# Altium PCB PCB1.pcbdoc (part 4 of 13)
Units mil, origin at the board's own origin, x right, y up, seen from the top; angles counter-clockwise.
Board outline 5895.51 x 5895.51 mil, 8 copper layers (Top Layer, L2_GND1, L3_SIG1, L4_GND2, L5_PWR, L6_SIG2, L7_GND3, Bottom Layer), stack 63.761 mil thick; 673 components, 558 nets, 2797 pads, 1861 vias.
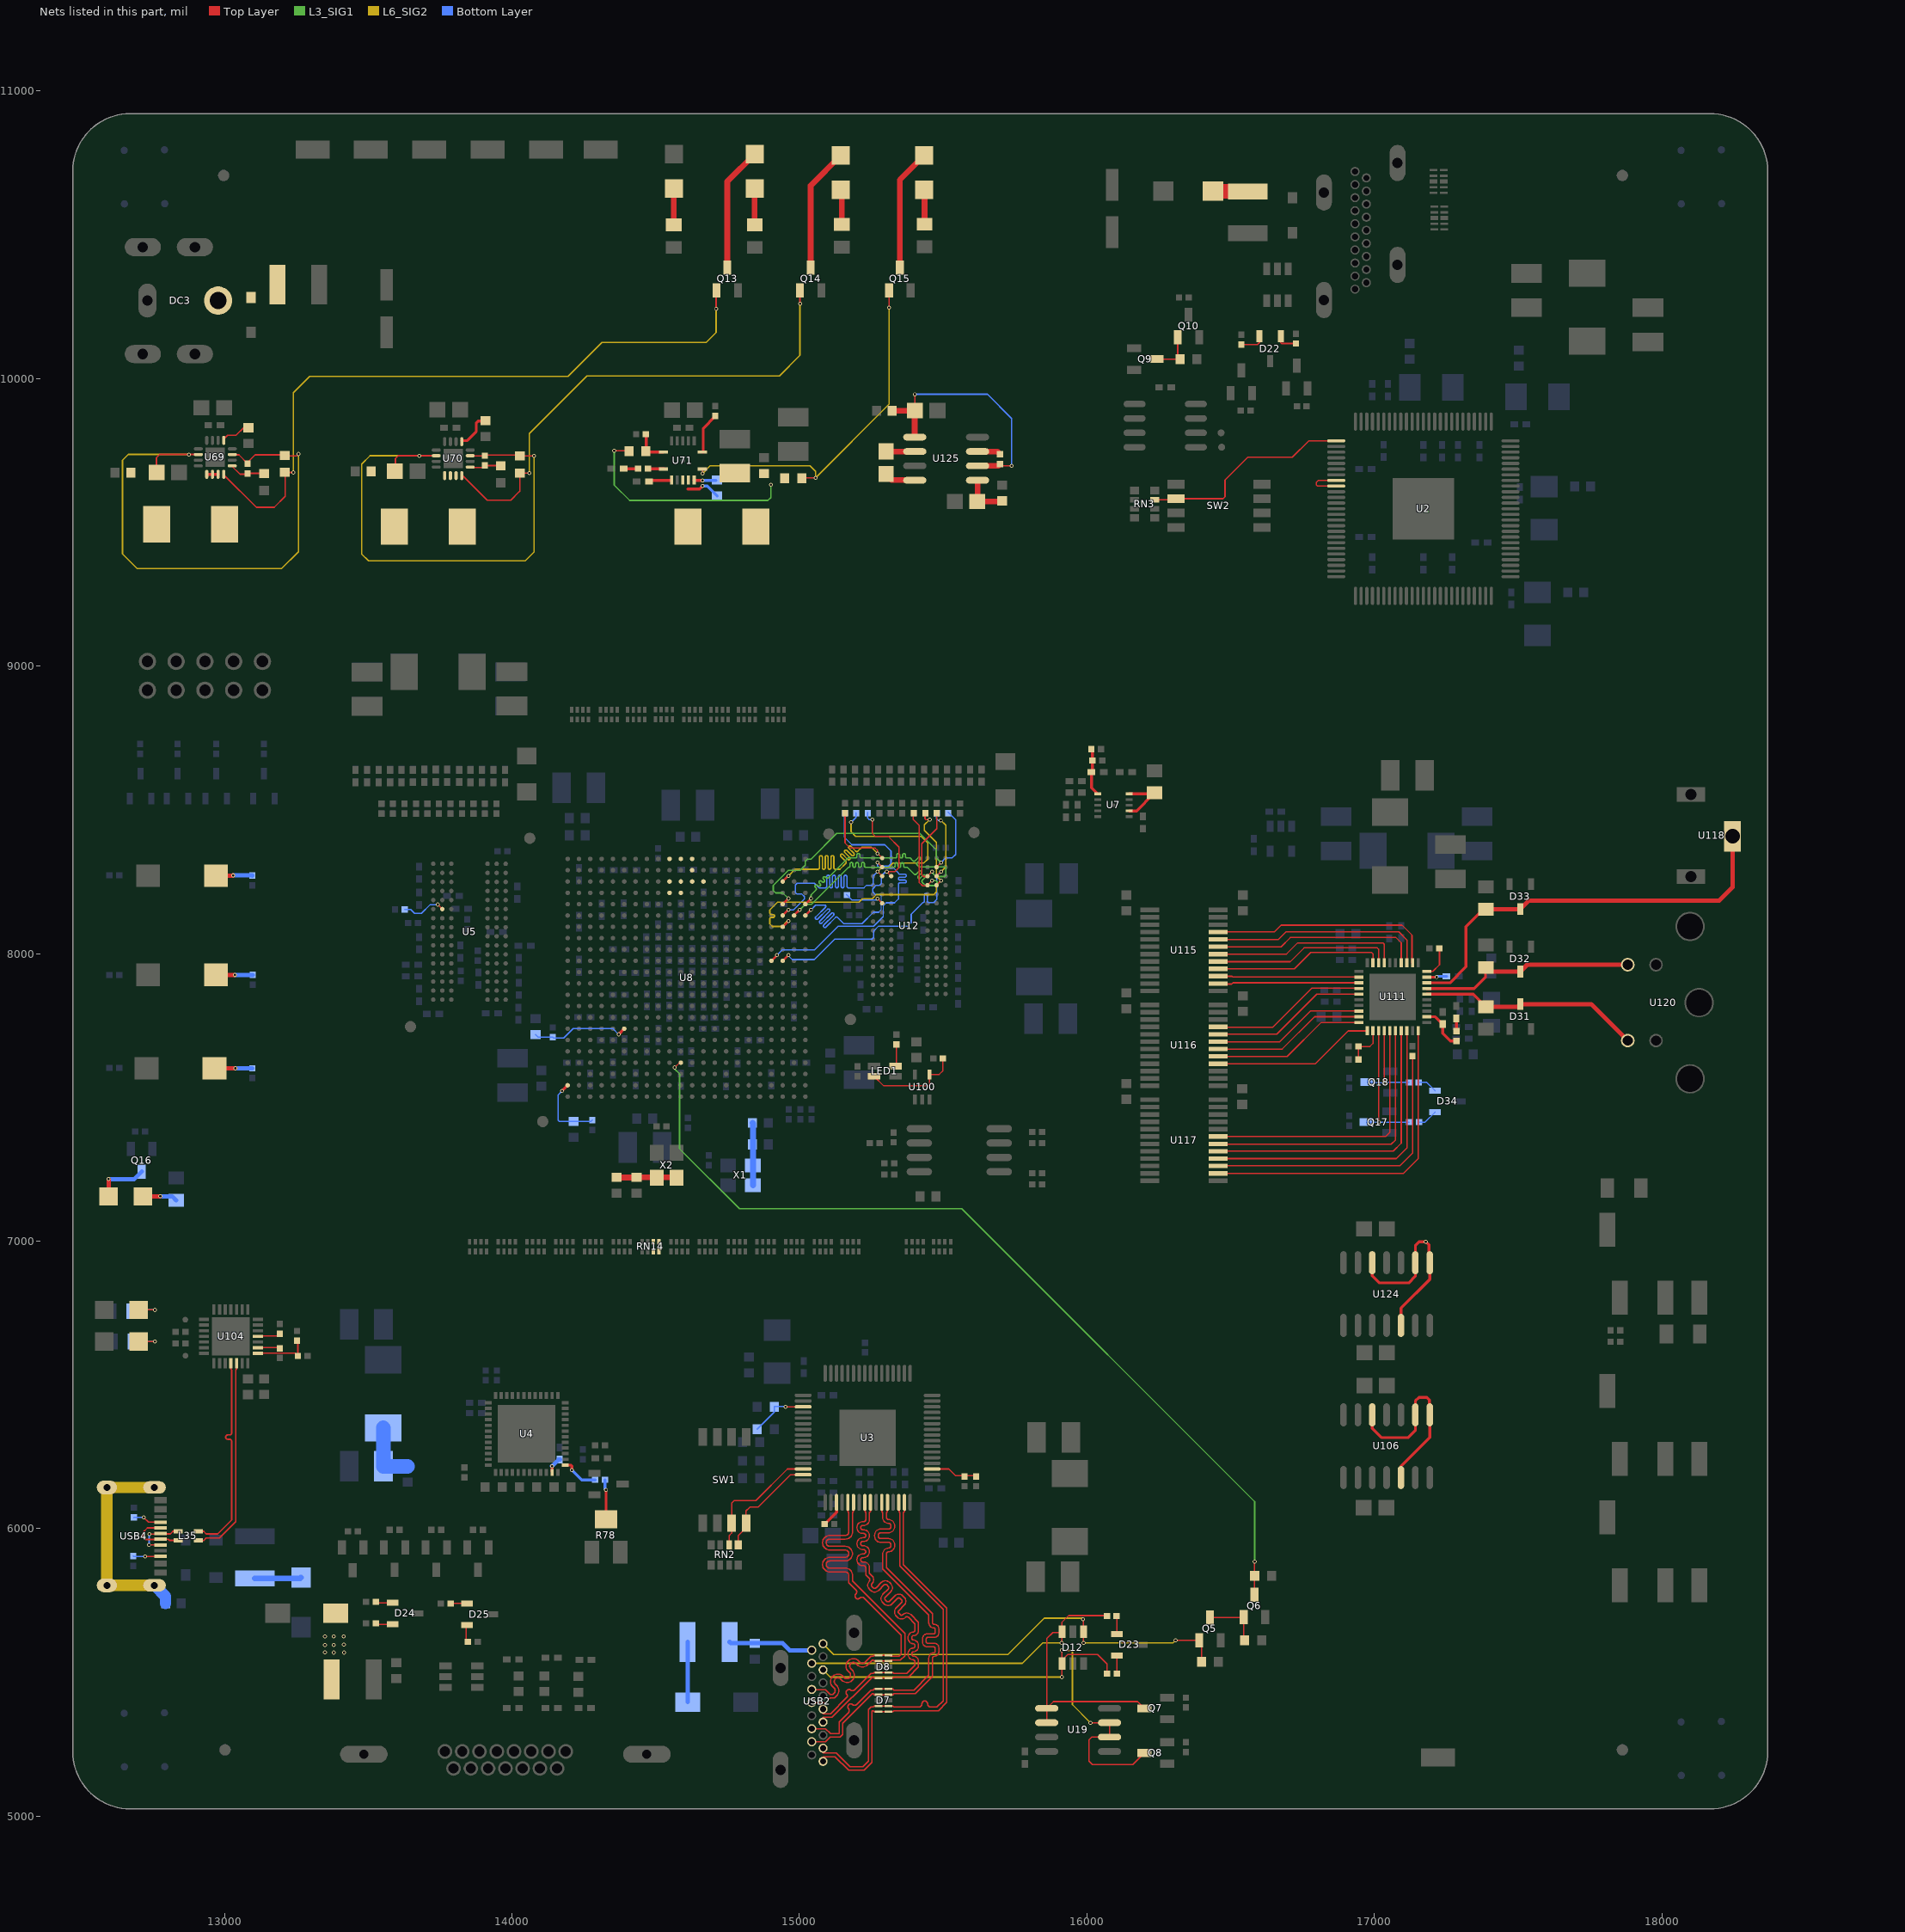
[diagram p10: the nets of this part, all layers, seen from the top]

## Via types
v1: diameter 23.62, hole 15.75, Top Layer to Bottom Layer, 621 vias
v2: diameter 13.8, hole 7.9, Top Layer to Bottom Layer, 567 vias
v3: diameter 13.78, hole 7.87, Top Layer to Bottom Layer, 529 vias
v4: diameter 13.78, hole 7.9, Top Layer to Bottom Layer, 114 vias
v5: diameter 15.75, hole 7.87, Top Layer to Bottom Layer, 16 vias
v6: diameter 24, hole 12, Top Layer to Bottom Layer, 10 vias
v7: diameter 11.81, hole 7.87, Top Layer to Bottom Layer, 4 vias

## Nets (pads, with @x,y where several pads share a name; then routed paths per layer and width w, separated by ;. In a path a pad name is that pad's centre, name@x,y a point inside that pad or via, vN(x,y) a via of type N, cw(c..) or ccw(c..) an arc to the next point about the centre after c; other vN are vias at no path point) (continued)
$1N10818: C3.2 R23.1 U8.T6 | length 343.4
  Top Layer w10: v2(14371.15,7719.16) U8.T6@14390.82,7738.84
  Bottom Layer w4.7: C3.2@14082.36,7718.44 14091.84,7708.96 R23.1@14142.36,7708.96 14145,7706.32 14180.38,7706.32 14213.06,7739 14351.31,7739 v2(14371.15,7719.16)
$1N14404: C4.2 R5.1 U8.AA1 | length 257.8
  Top Layer w10: v2(14174.29,7522.32) U8.AA1@14193.96,7542
  Bottom Layer w4.7: v2(14174.29,7522.32) 14160.52,7508.56 14160.52,7420.83 14164.83,7416.53 C4.2@14214.71,7416.53 14275.23,7416.53 R5.1@14279.71,7421.01
$1N21578: R26.1 U5.L8 | length 155
  Top Layer w4.7: v2(13742.12,8170.48) U5.L8@13757.87,8154.74
  Bottom Layer w4.7: R26.1@13627.58,8153.53 13647.83,8153.53 13661.36,8140 13685.36,8140 13715.84,8170.48 v2(13742.12,8170.48)
$1N30667: R53.1 U12.L8 | length 140
  Top Layer w4.7: v2@15272.12,8190.48 U12.L8@15287.87,8174.74
  Bottom Layer w4.7: R53.1@15164.01,8205.01 15182.88,8186.15 15267.78,8186.15 v2@15272.12,8190.48
  other v2: 15272.12,8190.6
$1N37312: R78.2 R80.2 | length 138.6
  Top Layer w10: R78.2@14327.36,6033.09 v3(14327.36,6135)
  Bottom Layer w10: R80.2@14323.4,6170 14323.4,6138.96 v3(14327.36,6135)
$1N37670: C110.1 U4.35 | length 57
  Top Layer w10: U4.35@14138.99,6198.75 14139.83,6199.58 v3(14139.83,6217.71)
  Bottom Layer w15: v3(14139.83,6217.71) 14162.01,6239.89 14166.76,6239.89 C110.1@14167.9,6241.03
$1N37860: R80.1 U4.37 | length 133.7
  Top Layer w10: U4.37@14185.22,6221.73 14185.95,6221 14205.36,6221 14208.36,6218 v3(14208.36,6204)
  Bottom Layer w10: v3(14208.36,6204) 14242.36,6170 R80.1@14289.32,6170
$1N45009: D5.1 U18.1
  other v3: 13415.19,5625.57
  other v4: 13380.45,5569.31 13415.81,5569.31 13349.7,5569.82 13349.7,5595.96 13380.45,5595.96 13415.43,5596.53 13349.7,5625.17 13380.96,5625.17
$1N52484: C119.1 R96.2 R97.2 U7.1 | length 167.5
  Top Layer w10: R96.2@16015.32,8711 16019.32,8707 R97.2@16019.32,8671 16019.32,8634.42 C119.1@16015.9,8631 16015.9,8576.75 U7.1@16037.24,8555.4
$1N52936: L1.1 U7.7 U7.10 | length 198.2
  Top Layer w10: U7.7@16147.47,8496.3 16172.7,8496.3 L1.1@16231.8,8555.4 ; U7.10@16147.47,8555.4 L1.1@16231.8,8555.4 ; L1.1@16235.36,8558.96 L1.1@16231.8,8555.4
$1N60209: R98.1 U3.19 | length 92.9
  Top Layer w10: R98.1@15087.32,6016 15129.09,6057.77 U3.19@15129.09,6091.59
$1N62286: R102.1 R103.2 U3.35 | length 163.2
  Top Layer w4.7: U3.35@15461.77,6207.73 15519.63,6207.73 15543.36,6184 15612.4,6184 R103.2@15614.36,6182.04
$1N62796: C148.2 U23.2 X2.1 X2.4 | length 209.8
  Top Layer w20: U23.2@14363.7,7221.6 C148.2@14433.7,7221.6 14572.28,7221.6 X2.1@14573.15,7220.73
$1N62811: C147.2 U22.2 X1.1 X1.4 | length 301.5
  Bottom Layer w4.7: C147.2@14837.09,7336 C147.2@14838.64,7334.45 ; U22.2@14837.14,7411.52 U22.2@14837.1,7411 14837.14,7337.8 14838.64,7336.3 C147.2@14839.47,7335.47 ; X1.4@14838.64,7258.59 X1.4@14842.39,7262.34
  Bottom Layer w20: U22.2@14837.1,7411 14838.64,7409.45 14838.64,7336.3 14838.64,7334.45 14838.64,7258.59 X1.1@14838.64,7194.53
$1N63393: D11.1 U24.1 | length 209
  Bottom Layer w15: D11.1@14611.36,5397 U24.1@14611.39,5606
$1N63667: Q5.3 Q6.1 U26.1 | length 199.9
  Top Layer w4.7: Q5.3@16427.98,5691.08 16544.32,5691.08 Q6.1@16545.58,5692.34 16545.58,5614.45 U26.1@16548.32,5611.71
$1N80606: U2.8 U2.9 | length 151.1
  Top Layer w4.7: U2.9@16867.21,9625.74 16802.62,9625.74 16798.36,9630 16798.36,9639 16804.78,9645.42 U2.8@16867.21,9645.42
$1N82813: Q9.3 Q10.1 U31.1 | length 159.8
  Top Layer w4.7: Q9.3@16242.63,10067.36 U31.1@16323.6,10067.36 16315.86,10075.1 Q10.1@16315.86,10142.99
$1N83117: D17.2 F1.1 | length 159.5
  Top Layer w50: D17.2@16438.67,10651 16595.33,10651 F1.1@16597.36,10648.97
$1N87324: L22.1 U69.1 U69.2 U69.3 | length 39.4
  Top Layer w10: U69.1@12938.75,9666.67 U69.2@12958.44,9666.67 U69.3@12978.12,9666.67
$1N87327: C195.2 U69.9 | length 100
  Top Layer w5: U69.9@12997.43,9788.7 13010.73,9802 13040.27,9802 13067.96,9829.7 C195.2@13080.4,9829.7
$1N87330: R134.2 R135.1 U69.5 | length 129.2
  Top Layer w5: U69.5@13025.39,9695.62 13054.14,9666.86 R135.1@13081.54,9666.86 ; R135.1@13080.36,9669.96 13141,9669.97 R134.2@13141.39,9669.58
$1N87338: C194.2 L22.2 L23.1 R133.2 R135.2 U69.7 U69.14 | length 2013.8
  Top Layer w5: C194.2@12762.71,9686.27 12763.75,9687.3 12763.75,9724.35 12775.04,9735.64 v3(12876.23,9735.64) 12908.48,9735.64 U69.14@12909.39,9734.73 ; U69.7@13025.39,9734.29 13050.65,9734.29 R135.2@13080.96,9703.98 ; R135.2@13079.02,9706.31 13107,9734.29 R133.2@13212.31,9734.29 ; R133.2@13211.73,9730.99 13251.18,9730.99 v3(13257.59,9737.4)
  L6_SIG2 w5: v3(12876.23,9735.64) 12665.61,9735.64 12645.43,9715.47 12645.43,9389.97 12696.59,9338.82 13198.99,9338.82 13257.59,9397.41 v3(13257.59,9737.4)
  Bottom Layer w5: v3(13257.59,9737.4) v3@13257.59,9738.18
$1N88386: L24.1 U70.1 U70.2 U70.3
$1N88389: C198.2 U70.9 | length 124.6
  Top Layer w10: U70.9@13825.8,9783.89 13844.75,9783.89 13875.94,9815.08 13875.94,9844.23 13883.22,9851.51 13904.5,9851.51 C198.2@13905.08,9852.1
$1N88392: R137.2 R138.1 U70.5 | length 118.5
  Top Layer w5: U70.5@13855.72,9689.87 13898.57,9689.87 13908.19,9699.48 13910.81,9696.86 R137.2@13969.1,9696.86
$1N88397: C197.2 L24.2 L25.1 R136.2 R138.2 U70.7 U70.14 | length 1896.6
  Top Layer w5: C197.2@13593.87,9673.91 13594.74,9674.78 13594.74,9721.56 13604.8,9731.62 U70.14@13736.4,9731.62 ; U70.7@13857.76,9730.67 R138.2@13905.85,9730.67 ; R138.2@13903.92,9733.26 14024.88,9733.26 R136.2@14025.76,9732.38 ; R136.2@14028.38,9728.01 14031.29,9730.93 v3(14077.35,9730.93)
  L6_SIG2 w5: v4(13677.81,9731.18) 13506.59,9731.18 13477.58,9702.17 13477.58,9389.05 13501.16,9365.48 14046.51,9365.48 14077.35,9396.31 v3(14077.35,9730.93)
$1N88827: R139.2 U71.1 | length 140.8
  Top Layer w10: U71.1@14665.56,9744.35 14665.56,9826.95 R139.2@14706.69,9868.08
$1N88869: C200.2 U71.9 | length 80
  Top Layer w10: C200.2@14476.25,9641.36 14480.42,9645.52 U71.9@14554.58,9645.52
$1N89025: R140.2 U71.8 | length 57.8
  Top Layer w10: R140.2@14471.94,9685.76 U71.8@14529.71,9685.76
$1N89029: C201.2 R140.1 | length 47.5
  Top Layer w10: C201.2@14389.38,9685.33 14436.59,9685.33 R140.1@14436.81,9685.11
$1N89111: C202.1 U71.13 | length 77.1
  Top Layer w10: U71.13@14632.4,9645.71 v3(14663.33,9645.71)
  Bottom Layer w10: v3(14663.33,9645.71) C202.1@14709.49,9645.71
$1N89126: C202.2 L26.1 U71.11 U71.12 | length 120.6
  Top Layer w10: 14611.5,9615.43 14652.85,9615.43 v3(14662.95,9625.53)
  Bottom Layer w10: v3(14662.95,9625.53) 14679.2,9625.53 C202.2@14713.67,9591.06
$1N89349: R141.2 R142.1 U71.7 | length 123.6
  Top Layer w10: R142.1@14464.54,9746.26 R142.1@14465.84,9744.97 ; R141.2@14466.91,9806.62 14466.91,9746.05 R142.1@14465.84,9744.97 ; U71.7@14525.12,9744.11 14466.7,9744.11 R142.1@14465.84,9744.97
$1N92548: R143.1 U77.2 | length 126.6
  Top Layer w20: R143.1@14563.18,10534.34 U77.2@14563.18,10660.93
$1N92638: R144.1 U78.2 | length 126.4
  Top Layer w20: R144.1@14844.36,10534.34 U78.2@14844.36,10660.74
$1N93481: Q13.3 U78.1 | length 434.2
  Top Layer w20: Q13.3@14749.36,10385.37 14749.36,10685.22 U78.1@14844.36,10780.22
$1N93486: Q13.1 R133.1 U69.4 | length 2362.2
  Top Layer w5: U69.4@12999.69,9663.8 13111.61,9551.88 13173.26,9551.88 13211.29,9589.92 13211.29,9670.36 13210.42,9671.24 13212.38,9673.19 v3(13239.94,9673.19) ; v3(14710.43,10241.74) 14710.43,10300.9 Q13.1@14711.3,10301.78
  L6_SIG2 w5: v3(13239.94,9673.19) 13239.94,9949.99 13296.81,10006.87 14194.9,10006.87 14313.43,10125.4 14675.96,10125.4 14710.43,10159.87 v3(14710.43,10241.74)
$1N93678: R145.1 U79.2 | length 122.1
  Top Layer w20: U79.2@15144.36,10656.26 15147.36,10653.26 R145.1@15147.36,10535.37
$1N93680: Q14.3 U79.1 | length 433.9
  Top Layer w20: Q14.3@15039.36,10385.37 15039.36,10670.74 U79.1@15144.36,10775.74
$1N93699: Q14.1 R136.1 U70.4 | length 1772.7
  Top Layer w5: U70.4@13827.04,9663.81 13914.45,9576.4 13996.01,9576.4 14025.74,9606.13 14027.93,9606.13 14027.93,9670.84 14060.13,9670.84 v3(14060.3,9671.01) ; Q14.1@15000.94,10314.4 15001.99,10313.35 v3(15001.99,10259.57)
  L6_SIG2 w5: v3(14060.3,9671.01) 14060.3,9808.64 14260.65,10009 14930.32,10009 15001.99,10080.67 v3(15001.99,10259.57)
$1N93752: C206.2 L26.2 L27.1 R142.2 R146.2 | length 784.3
  Top Layer w5: v3(14356.08,9748.56) 14356.47,9748.17 R142.2@14405.43,9748.17
  L3_SIG1 w5: v3(14356.08,9748.56) 14356.08,9629.42 14409.63,9575.86 14890.88,9575.86 14900.83,9585.81 v3(14900.83,9630.4)
$1N93902: R147.1 U80.2 | length 120.3
  Top Layer w20: U80.2@15434.36,10656.26 15435.36,10655.26 R147.1@15435.36,10536.37
$1N93904: Q15.3 U80.1 | length 425.6
  Top Layer w20: Q15.3@15349.36,10385.37 15349.36,10690.74 U80.1@15434.36,10775.74
$1N93914: Q15.1 R146.1 U71.14 | length 1259.1
  Top Layer w5: v3(14662.94,9669.34) U71.14@14662.94,9685.27 ; R146.1@15009.06,9654.28 15055.98,9654.28 v3(15056.51,9654.81) ; Q15.1@15310.3,10309.03 15312.41,10306.92 v3(15312.41,10245.9)
  L6_SIG2 w5: v3(14662.94,9669.34) 14689.48,9695.88 15037.37,9695.88 15056.51,9676.74 v3(15056.51,9654.81) 15312.41,9910.71 v3(15312.41,10245.9)
$1N104683: D20.1 DC3.3 F2.2
$1N105607: R148.1 U81.2 | length 121.2
  Top Layer w15: U81.2@12717.1,7156 v3(12777.36,7156)
  Bottom Layer w15: v3(12777.36,7156) 12817.99,7156 R148.1@12832.36,7141.63
$1N105608: Q16.3 U81.1 | length 185.7
  Top Layer w15: v3(12597.36,7216) 12597.36,7156.26 U81.1@12597.62,7156
  Bottom Layer w15: v3(12597.36,7216) 12686.73,7216 Q16.3@12712.36,7241.63
$1N105776: R196.2 SW3.2 | length 127.7
  Top Layer w15: SW3.2@12970.47,8271 13029.36,8271 v3(13030.36,8272)
  Bottom Layer w15: v3(13030.36,8272) 13096.4,8272 R196.2@13097.36,8271.04
$1N106443: C216.2 L32.2 L33.1 | length 218.7
  Bottom Layer w50: L32.2@13552.55,6351.08 13553.1,6350.53 C216.2@13553.1,6217 13553.54,6216.56 L33.1@13637.36,6216.56
$1N164530: D22.2 R111.2 | length 88.1
  Top Layer w4.7: R111.2@16537.36,10117.96 16593.32,10117.96 16600.36,10125 16600.36,10146.42 D22.2@16599.79,10146.98
$1N164545: D22.1 R110.1 | length 76.9
  Top Layer w4.7: D22.1@16674.59,10146.98 16674.36,10146.75 16674.36,10124 16676.77,10121.58 R110.1@16727.19,10121.58
$1N164557: D23.1 R106.1 | length 63.5
  Top Layer w4.7: R106.1@16103.4,5697 16103.95,5696.45 D23.1@16103.95,5633.73
$1N164561: D23.2 R107.2 | length 62.8
  Top Layer w4.7: D23.2@16103.95,5558.93 16104.35,5558.53 R107.2@16104.35,5496.33
$1N164584: D24.2 R91.2 | length 63.8
  Top Layer w4.7: R91.2@13528.4,5667.67 13589.83,5667.67 D24.2@13591.49,5666.01
$1N164596: D24.1 R90.1 | length 60.6
  Top Layer w4.7: R90.1@13526.08,5746.04 13529.62,5742.5 D24.1@13585.19,5742.5
$1N164661: D25.1 R94.1 | length 57.3
  Top Layer w4.7: R94.1@13787.4,5740 13843.75,5740 D25.1@13844.41,5739.35
$1N164665: D25.2 R95.2 | length 63.8
  Top Layer w4.7: R95.2@13841.35,5604.79 13841.35,5663.23 D25.2@13845.12,5667
$1N212426: LED1.3 R154.2 U100.4 | length 338.5
  Top Layer w4.7: LED1.3@15259.96,7573.28 15293.24,7540 15448.36,7540 15452.95,7544.59 U100.4@15452.95,7579.31 15453.64,7580 15486.36,7580 15499.4,7593.04 R154.2@15499.4,7636
$1N226069: U3.3 U101.1 U102.2 | length 203.7
  Top Layer w4.7: v3(14951.36,6424.27) U3.3@15012.95,6424.27
  Bottom Layer w4.7: U102.2@14853.32,6346.36 14912.64,6405.68 U101.1@14912.64,6424.06 14913.58,6425 14951.36,6425 v3(14951.36,6424.27)
$1N298643: R197.2 SW4.2 | length 127.9
  Top Layer w15: SW4.2@12970.47,7926 v3(13036.36,7926)
  Bottom Layer w15: v3(13036.36,7926) R197.2@13098.32,7926
$1N298747: R198.2 SW5.2 | length 131.9
  Top Layer w15: SW5.2@12965.47,7601 v3(13038.36,7601)
  Bottom Layer w15: v3(13038.36,7601) R198.2@13097.32,7601
$1N329198: U8.D10
$1N329200: U8.C10
$1N329204: U8.A10
$1N329206: U8.C11
$1N329208: U8.A11
$1N329210: U8.D11
$1N329212: U8.C12
$1N329214: U8.B12
$1N329216: U8.A12
$1N329253: U8.C13
$1N373188: LED1.1 R185.2 | length 76.3
  Top Layer w4.7: LED1.1@15334.76,7608.72 15337.36,7611.31 R185.2@15337.36,7683.96
$1N419363: RN14.3
$1N419365: RN14.4
$1N419415: RN14.6
$1N419417: RN14.5
$2N4528: R157.1 R158.2 U104.8 | length 198
  Top Layer w4: U104.8@13116.29,6609.86 U104.8@13116.85,6610.42 ; R157.1@13245.79,6610.42 R157.1@13246.35,6609.86
  Top Layer w4.7: U104.8@13116.85,6610.42 13117.03,6610.6 13245.61,6610.6 R157.1@13245.79,6610.42 ; R157.1@13246.35,6609.86 R157.1@13255.65,6600.56 13255.65,6650.56 R158.2@13252.69,6653.52
$2N4529: R31.2 U104.9 | length 77.2
  Top Layer w4.7: U104.9@13116.29,6629.54 13190.75,6629.54 R31.2@13192.69,6627.6
$2N4531: U104.11 U105.1 | length 76.5
  Top Layer w4.7: U104.11@13119.47,6670.56 13184.73,6670.56 U105.1@13192.69,6678.52
$2N4874: L35.1 USB4.6 USB4.8 | length 160.4
  Top Layer w5.1: v3(12738.2,5943.51) 12738.39,5943.71 USB4.8@12778.52,5943.71 ; v3(12738.86,5981.15) 12776.59,5981.15 USB4.6@12778.52,5983.08 ; 12800.85,5982.03 12811.93,5982.03 12820.6,5990.7 L35.1@12838.89,5990.7
  Bottom Layer w5.1: v3(12738.2,5943.51) 12738.2,5980.48 v3(12738.86,5981.15)
$2N4875: L35.2 USB4.5 USB4.7 | length 210.3
  Top Layer w5.1: USB4.7@12778.05,5962.55 12726.69,5962.55 12716.73,5972.51 12716.73,5986.9 12732.58,6002.76 USB4.5@12778.52,6002.76 ; USB4.7@12778.52,5963.39 12805.4,5963.39 12809.52,5959.26 L35.2@12838.95,5959.26
$2N4881: R121.1 USB4.10 | length 91.4
  Top Layer w4.7: v3(12724.5,5903.88) USB4.10@12773.87,5903.88
  Bottom Layer w4.7: R121.1@12682.88,5904.77 12683.76,5903.88 v3(12724.5,5903.88)
$2N4882: R120.1 USB4.4 | length 101.4
  Top Layer w4.7: v3(12719.85,6039.09) 12735.94,6023.01 USB4.4@12779.18,6023.01
  Bottom Layer w4.7: R120.1@12684.73,6038.35 12685.46,6039.09 v3(12719.85,6039.09)
$2N4887: L36.1 USB4.13 USB4.14 | length 750
  L6_SIG2 w40: USB4.14@12756.86,5802.95 USB4.14@12591.51,5802.96 USB4.13@12591.51,6143.51 USB4.13@12756.87,6143.5
  Bottom Layer w40: USB4.14@12756.86,5802.95 12795.25,5764.58 L36.1@12795.25,5740.16
$2N5766: D29.2 F3.1 | length 162
  Bottom Layer w20: F3.1@13105.67,5827.26 13263.3,5827.26 D29.2@13266.36,5830.32
$2N6016: R164.1 U108.2 | length 129.2
  Top Layer w4.7: U108.2@12702.1,6651 v3(12758.36,6651)
  Bottom Layer w4.7: R164.1@12685.47,6651 v3(12758.36,6651)
$2N6092: R165.1 U109.2 | length 135
  Top Layer w4.7: U109.2@12702.1,6761 v3(12758.36,6761)
  Bottom Layer w4.7: R165.1@12681.73,6756 12686.73,6761 v3(12758.36,6761)
$2N13136: C341.1 R173.1 U111.22 | length 157
  Top Layer w10: U111.22@17181.77,7780.37 17211.53,7780.37 C341.1@17237.36,7754.54 17237.36,7723 17264.4,7695.96 R173.1@17285.36,7695.96
$2N13145: C342.1 R173.2 | length 44.5
  Top Layer w10: C342.1@17285.07,7774.42 17285.07,7730.33 R173.2@17285.36,7730.04
$2N15480: D34.1 R182.1 | length 69.9
  Bottom Layer w4.7: R182.1@17155.4,7414 17176.4,7414 D34.1@17211,7448.6
$2N15481: D34.2 R183.2 | length 68.4
  Bottom Layer w4.7: R183.2@17154.4,7552 17182.4,7552 D34.2@17211,7523.4
$3N1865: C353.2 U125.2 | length 92.9
  Top Layer w20: C353.2@15302.45,9743.07 15305.22,9745.84 15392.15,9745.84 U125.2@15393.61,9744.38
$3N1869: C353.1 U125.4 | length 106.7
  Top Layer w20: C353.1@15298.52,9669.62 15321.57,9646.57 U125.4@15395.67,9646.57
$3N1948: R195.2 U125.7 | length 82.4
  Top Layer w20: U125.7@15619.51,9746 15688.12,9746 R195.2@15697.85,9736.27
$3N2377: C351.2 L44.2 R195.1 U125.1 U125.6 | length 888
  Top Layer w5: C351.2@15401.21,9887.92 v3(15401.21,9945) ; R195.1@15697.85,9702.19 15704.04,9696 v3(15738.36,9696)
  Top Layer w20: L44.2@15323.11,9887.91 15401.19,9887.91 U125.1@15401.21,9796 ; U125.6@15619.51,9696 15691.66,9696 R195.1@15697.85,9702.19
  Bottom Layer w5: v3(15401.21,9945) 15654.36,9945 15738.36,9861 v3(15738.36,9696)
$3N2455: C352.2 L45.1 U125.5 | length 157.9
  Top Layer w20: U125.5@15619.51,9646 15619.51,9573.15 C352.2@15618.82,9572.47 15702.02,9572.47 L45.1@15702.66,9573.11
$3N2639: U106.1 U106.2 U106.5 U106.12 | length 693.2
  Top Layer w10: U106.5@16992.36,6396.02 16992.36,6349 17024.36,6317 17118.36,6317 17142.36,6341 U106.2@17142.36,6396.02 17142.36,6444 17155.36,6457 17182.36,6457 17191.36,6448 17191.36,6397.02 U106.1@17192.36,6396.02 17192.36,6318 17092.36,6218 U106.12@17092.36,6177.98
$3N2658: U124.1 U124.2 U124.5 U124.12 | length 701.6
  Top Layer w10: U124.5@16992.36,6925.02 16992.36,6879.9 17017.26,6855 17119.36,6855 17142.36,6878 U124.2@17142.36,6925.02 17142.36,6985 17155.36,6998 v4(17178.36,6998) 17189.36,6987 17189.36,6928.02 U124.1@17192.36,6925.02 17192.36,6867 17092.36,6767 U124.12@17092.36,6706.98
ADV7393_ALSB: R171.1 R172.1 U111.12 | length 143.8
  Top Layer w4.7: R171.1@16944.08,7631.79 R172.1@16944.08,7676.79 16944.29,7677 16984.36,7677 16994.76,7687.4 U111.12@16994.76,7731.16
ADV7393_CMP: U111.29 U112.1 | length 70.3
  Top Layer w10: U111.29@17181.77,7918.17 v3(17216.36,7918.17)
  Bottom Layer w10: v3(17216.36,7918.17) 17219.19,7921 U112.1@17250.9,7921
ADV7393_DAC1: D33.3 R174.1 U111.28 U118.1 | length 1460.7
  Top Layer w10: U111.28@17181.77,7898.48 17262.84,7898.48 17318.36,7954 17318.36,8094 17377.99,8153.63 R174.1@17387.36,8153.63
  Top Layer w15: R174.1@17387.36,8153.63 17388.37,8154.64 D33.3@17507.36,8154.64 17537.41,8184.69 18199.51,8184.69 18245.44,8230.63 U118.1@18245.44,8408.1
ADV7393_DAC2: D32.3 R175.2 U111.27 U120.4 | length 764.7
  Top Layer w10: U111.27@17181.77,7878.8 17347.16,7878.8 17386.36,7918 17386.36,7950.63 R175.2@17387.36,7951.63
  Top Layer w15: R175.2@17386.36,7950.63 17399.35,7937.64 D32.3@17507.36,7937.64 17531.02,7961.3 U120.4@17881.05,7961.3
ADV7393_DAC3: D31.3 R176.2 U111.26 U120.3 | length 773.7
  Top Layer w10: U111.26@17181.77,7859.11 17343.62,7859.11 R176.2@17387.36,7815.37
  Top Layer w15: R176.2@17387.36,7815.37 17498.37,7815.37 D31.3@17507.36,7824.36 17754.21,7824.36 U120.3@17881.05,7697.52
ADV7393_HS: U111.33 U115.20 | length 745.9
  Top Layer w4.7: U115.20@16469.8,8048.64 16470.23,8049.08 16665.98,8049.08 16692.36,8075.45 17084.98,8075.45 17112.87,8047.56 U111.33@17112.87,7967.38
ADV7393_P0: U111.34 U115.19 | length 710.3
  Top Layer w4.7: U115.19@16474.05,8023.28 16474.35,8023.59 16675.21,8023.59 16707.33,8055.7 17075.1,8055.7 17093.19,8037.61 U111.34@17093.19,7967.38
ADV7393_P1: U111.37 U115.18 | length 636.3
  Top Layer w4.7: U115.18@16480.95,7998.54 16694.44,7998.54 16733.14,8037.24 17029.43,8037.24 17034.13,8032.54 U111.37@17034.13,7967.38
ADV7393_P2: U111.38 U115.17 | length 615.3
  Top Layer w4.7: U115.17@16468.99,7971.78 16707.21,7971.78 16755.44,8020 17009.75,8020 17014.45,8015.3 U111.38@17014.45,7967.38
ADV7393_P3: U111.39 U115.16 | length 573.7
  Top Layer w4.7: U115.16@16478.84,7946.24 16479.6,7947 16721.85,7947 16778.85,8004 16990.06,8004 16994.76,7999.3 U111.39@16994.76,7967.38
ADV7393_P4: U111.2 U115.15 | length 466.9
  Top Layer w4.7: U115.15@16479.92,7921.3 16480.22,7921 16504.36,7921 16507.19,7918.17 U111.2@16945.55,7918.17
ADV7393_P5: U111.3 U115.14 | length 474.8
  Top Layer w4.7: U115.14@16472.91,7894.69 16473.6,7894 16503.36,7894 16507.84,7898.48 U111.3@16945.55,7898.48
ADV7393_P6: U111.4 U116.21 | length 526.1
  Top Layer w4.7: U116.21@16476.24,7744.2 16476.44,7744 16646.36,7744 16782.16,7879.8 16944.55,7879.8 U111.4@16945.55,7878.8
ADV7393_P7: U111.5 U116.20 | length 530.1
  Top Layer w4.7: U116.20@16473.09,7720 16660.36,7720 16799.47,7859.11 U111.5@16945.55,7859.11
ADV7393_P8: U111.8 U116.19 | length 512.6
  Top Layer w4.7: U116.19@16477.49,7693.58 16478.07,7693 16670.36,7693 16777.42,7800.06 U111.8@16945.55,7800.06
ADV7393_P9: U111.9 U116.18 | length 511
  Top Layer w4.7: U116.18@16481.17,7667.87 16481.3,7668 16679.36,7668 16791.73,7780.37 U111.9@16945.55,7780.37
ADV7393_P10: U111.10 U116.17 | length 526.7
  Top Layer w4.7: U116.17@16468.1,7641.9 16468.2,7642 16696.36,7642 16815.05,7760.69 U111.10@16945.55,7760.69
ADV7393_P11: U111.11 U116.16 | length 548
  Top Layer w4.7: U116.16@16474.41,7617 16794.36,7617 16908.52,7731.16 U111.11@16975.08,7731.16
ADV7393_P12: U111.15 U117.19 | length 936.2
  Top Layer w4.7: U117.19@16476.47,7364.51 16476.98,7364 17039.23,7364 17053.82,7378.59 U111.15@17053.82,7731.16
ADV7393_P13: U111.16 U117.18 | length 986.6
  Top Layer w4.7: U117.18@16472.16,7337.02 17058.36,7337 17073.5,7352.14 U111.16@17073.5,7731.16
ADV7393_P14: U111.17 U117.17 | length 1036
  Top Layer w4.7: U117.17@16459.21,7312.72 16459.49,7313 17065.36,7313 17093.19,7340.83 U111.17@17093.19,7731.16
ADV7393_P15: U111.18 U117.16 | length 1062.1
  Top Layer w4.7: U117.16@16473.98,7287.96 16474.94,7287 17076.36,7287 17112.87,7323.51 U111.18@17112.87,7731.16
ADV7393_RESET: U111.20 U117.14 | length 1141.5
  Top Layer w4.7: U117.14@16476.68,7235.34 16477.01,7235 17100.36,7235 17152.24,7286.88 U111.20@17152.24,7731.16
ADV7393_RSET: R170.1 U111.30 | length 111.6
  Top Layer w4.7: U111.30@17181.77,7937.85 17203.21,7937.85 17226.36,7961 17226.36,8017.04 R170.1@17225.4,8018
ADV7393_SCL: Q18.3 R183.1 U111.14 | length 325.3
  Top Layer w4.7: v3(17034.13,7552) U111.14@17034.13,7731.16
  Bottom Layer w4.7: Q18.3@16975.99,7553 16977.99,7551 17034.13,7551 v3(17034.13,7552) R183.1@17120.32,7552
ADV7393_SDA: Q17.3 R182.2 U111.13 | length 465.9
  Top Layer w4.7: U111.13@17014.45,7731.16 17014.45,7414.91 v3(17015.36,7414)
  Bottom Layer w4.7: Q17.3@16972.99,7414 v3(17015.36,7414) R182.2@17121.32,7414
ADV7393_VS: U111.32 U115.21 | length 788.1
  Top Layer w4.7: U115.21@16464.55,8074.61 16465.1,8075.16 16651.41,8075.16 16675.13,8098.88 17095.9,8098.88 17130.59,8064.18 U111.32@17130.59,7966.57
BSEL: RN2.5 SW1.4 U3.15 | length 379.6
  Top Layer w4.7: RN2.5@14787.6,5944.44 14787.36,5944.68 14787.36,5976 14814.36,6003 SW1.4@14814.36,6019 14814.36,6062 14827.36,6075 14856.36,6075 14969.41,6188.05 U3.15@15012.95,6188.05
BUFFER_27M_OUT: R177.1 U117.15 | length 1019.8
  Top Layer w4.7: U117.15@16469.13,7262.96 16470.09,7262 17088.36,7262 17132.36,7306 R177.1@17132.36,7643.96
D+: L35.4 U104.4 | length 714.8
  Top Layer w5.1: L35.4@12909.82,5990.76 12928.12,5990.76 12936.83,5982.05 12977.25,5982.05 13025.48,6030.28 13025.48,6303.64 ccw(c13017.98,6303.64) 13017.98,6311.14 13011.86,6311.14 cw(c13011.86,6318.64) 13011.86,6326.14 13017.98,6326.14 ccw(c13017.98,6333.64) 13025.48,6333.64 13025.48,6552.15 13022.69,6554.94 U104.4@13022.69,6575.31
D-: L35.3 U104.5 | length 708.8
  Top Layer w5.1: L35.3@12909.8,5959.24 12928.12,5959.24 12936.83,5967.95 12983.09,5967.95 13039.58,6024.44 13039.58,6552.15 13042.38,6554.94 U104.5@13042.38,6575.31
DFO: RN3.7 SW2.2 U2.1 | length 749.9
  Top Layer w4.7: RN3.7@16236.01,9578.75 16306.11,9578.75 SW2.2@16309.36,9582 16473.36,9582 16480.36,9589 16480.36,9647 16559.36,9726 16714.36,9726 16771.58,9783.22 U2.1@16867.21,9783.22
DSEL: RN2.6 SW1.3 U3.14 | length 445.8
  Top Layer w4.7: RN2.6@14756.11,5944.44 14756.36,5944.69 14756.36,5977 14764.36,5985 SW1.3@14764.36,6019 14764.36,6089 14773.36,6098 14848.36,6098 14958.09,6207.73 U3.14@15012.95,6207.73
DVI_5V: C149.2 U24.2 USB2.18 | length 297.3
  Bottom Layer w15: U24.2@14757.33,5606 14761.77,5601.56 C149.2@14844.36,5601.56 14941.8,5601.56 14965.82,5577.54 USB2.18@15042.85,5577.54
DVI_C_CLK+: D8.4 D8.7 U3.22 USB2.10 | length 1423.5
  Top Layer w4: USB2.10@15041.04,5395.8 15092.3,5395.8 15107.49,5410.99 15122.02,5410.99 15129.94,5418.91 ccw(c15111.91,5436.94) 15129.94,5454.97 15124.9,5460.02 cw(c15133.74,5468.86) 15142.58,5477.7 15147.62,5472.65 ccw(c15165.65,5490.68) 15183.68,5508.71 15178.64,5513.76 cw(c15187.48,5522.6) 15196.32,5531.44 15201.36,5526.39 ccw(c15219.39,5544.42) 15237.42,5526.39 15254.05,5543.02 15256.05,5543.02 15259.38,5539.68 D8.7@15274.77,5539.68 D8.4@15310.83,5539.68 ; U3.22@15188.15,6091.59 15188.15,6060.06 15184.8,6056.72 15184.8,5989.32 cw(c15159.3,5989.32) 15159.3,5963.82 15105.82,5963.82 ccw(c15105.82,5951.32) 15105.82,5938.82 15159.3,5938.82 cw(c15159.3,5913.32) 15159.3,5887.82 15105.82,5887.82 ccw(c15105.82,5875.32) 15105.82,5862.82 15159.3,5862.82 cw(c15159.3,5837.32) 15184.8,5837.32 15184.8,5817.66 15367.15,5635.31 15367.15,5558.61 15351.56,5543.02 15318.16,5543.02 15314.83,5539.68 D8.4@15310.83,5539.68 ; D8.4@15311.76,5538.75 D8.4@15310.83,5539.68
DVI_C_CLK-: D8.5 D8.6 U3.21 USB2.12 | length 1420.2
  Top Layer w4: USB2.12@15046.79,5440.1 15091.38,5440.1 15107.49,5423.99 15116.63,5423.99 15120.75,5428.1 ccw(c15111.91,5436.94) 15120.75,5445.78 15115.71,5450.83 cw(c15133.74,5468.86) 15151.77,5486.89 15156.81,5481.84 ccw(c15165.65,5490.68) 15174.49,5499.52 15169.45,5504.57 cw(c15187.48,5522.6) 15205.51,5540.63 15210.55,5535.58 ccw(c15219.39,5544.42) 15228.23,5535.58 15248.66,5556.02 15256.05,5556.02 15259.38,5559.35 D8.6@15274.77,5559.35 15308.74,5559.35 D8.5@15310.14,5560.76 ; U3.21@15168.46,6091.59 15168.46,6060.06 15171.8,6056.72 15171.8,5989.32 cw(c15159.3,5989.32) 15159.3,5976.82 15105.82,5976.82 ccw(c15105.82,5951.32) 15105.82,5925.82 15159.3,5925.82 cw(c15159.3,5913.32) 15159.3,5900.82 15105.82,5900.82 ccw(c15105.82,5875.32) 15105.82,5849.82 15159.3,5849.82 cw(c15159.3,5837.32) 15171.8,5837.32 15171.8,5812.28 15196.61,5787.47 cw(c15189.54,5780.4) 15196.61,5773.33 15196.35,5773.06 ccw(c15203.42,5765.99) 15210.49,5758.92 15210.75,5759.18 cw(c15217.83,5752.11) 15224.9,5759.18 15354.15,5629.93 15354.15,5563.99 15346.18,5556.02 15318.16,5556.02 15314.83,5559.35 D8.5@15309.42,5559.35
DVI_C_D0+: D8.1 D8.10 U3.25 USB2.7 | length 1424.5
  Top Layer w4: USB2.7@15082.22,5327.46 15082.22,5342.29 15083.63,5343.7 15113.8,5343.7 15254.05,5483.95 15256.05,5483.95 15259.38,5480.61 D8.10@15274.77,5480.61 15303.88,5480.61 D8.1@15303.99,5480.5 ; U3.25@15247.2,6091.59 15247.2,6060.06 15243.86,6056.72 15243.86,6032.03 cw(c15223.36,6032.03) 15223.36,6011.53 15220.54,6011.53 ccw(c15220.54,6004.03) 15220.54,5996.53 15223.36,5996.53 cw(c15223.36,5976.03) 15223.36,5955.53 15220.54,5955.53 ccw(c15220.54,5948.03) 15220.54,5940.53 15223.36,5940.53 cw(c15223.36,5920.03) 15223.36,5899.53 15220.54,5899.53 ccw(c15220.54,5892.03) 15220.54,5884.53 15223.36,5884.53 cw(c15223.36,5864.03) 15243.86,5864.03 15243.86,5845.15 15252.35,5836.66 cw(c15238.37,5822.68) 15252.35,5808.7 ccw(c15257.14,5803.91) 15252.35,5799.12 15256.92,5794.55 ccw(c15261.71,5799.34) 15266.5,5794.55 15285.27,5813.32 cw(c15299.25,5799.34) 15313.23,5813.32 15317.79,5808.76 cw(c15303.81,5794.78) 15317.79,5780.8 15299.02,5762.03 ccw(c15303.81,5757.24) 15299.02,5752.45 15303.59,5747.88 ccw(c15308.38,5752.67) 15313.17,5747.88 15331.93,5766.65 cw(c15345.92,5752.67) 15359.9,5766.65 15364.46,5762.09 cw(c15350.48,5748.11) 15364.46,5734.13 15345.69,5715.36 ccw(c15350.48,5710.57) 15345.69,5705.78 15350.26,5701.22 ccw(c15355.05,5706) 15359.83,5701.22 cw(c15373.82,5687.23) 15387.8,5701.22 15414.28,5674.73 15414.28,5646 cw(c15396.23,5646) 15396.23,5627.96 ccw(c15396.23,5622.91) 15391.19,5622.91 15391.19,5618 ccw(c15396.23,5618) 15396.23,5612.96 cw(c15396.23,5594.91) 15414.28,5594.91 15414.28,5590 cw(c15396.23,5590) 15396.23,5571.96 ccw(c15396.23,5566.91) 15391.19,5566.91 15391.19,5562 ccw(c15396.23,5562) 15396.23,5556.96 cw(c15396.23,5538.91) 15414.28,5538.91 15414.28,5519.25 15378.98,5483.95 15328.15,5483.95 15324.81,5480.61 D8.1@15309.43,5480.61
DVI_C_D0-: D8.2 D8.9 U3.24 USB2.9 | length 1427.4
  Top Layer w4: USB2.9@15082.22,5372.93 15082.22,5358.12 15083.63,5356.7 15108.42,5356.7 15164.53,5412.82 ccw(c15158.64,5418.72) 15164.53,5424.61 cw(c15170.43,5430.51) 15164.53,5436.41 15166.88,5438.76 cw(c15172.78,5432.86) 15178.68,5438.76 ccw(c15184.57,5444.65) 15190.47,5438.76 15248.66,5496.95 15256.05,5496.95 15259.38,5500.28 D8.9@15274.77,5500.28 D8.2@15309.43,5500.28 15324.81,5500.28 15328.15,5496.95 15373.59,5496.95 15401.28,5524.63 15401.28,5538.91 ccw(c15396.23,5538.91) 15396.23,5543.96 cw(c15396.23,5562) 15378.19,5562 15378.19,5566.91 cw(c15396.23,5566.91) 15396.23,5584.96 ccw(c15396.23,5590) 15401.28,5590 15401.28,5594.91 ccw(c15396.23,5594.91) 15396.23,5599.96 cw(c15396.23,5618) 15378.19,5618 15378.19,5622.91 cw(c15396.23,5622.91) 15396.23,5640.96 ccw(c15396.23,5646) 15401.28,5646 15401.28,5669.35 15378.6,5692.02 ccw(c15373.82,5687.23) 15369.03,5692.02 cw(c15355.05,5706) 15341.06,5692.02 15336.5,5696.59 cw(c15350.48,5710.57) 15336.5,5724.55 15355.27,5743.32 ccw(c15350.48,5748.11) 15355.27,5752.9 15350.7,5757.46 ccw(c15345.92,5752.67) 15341.13,5757.46 15322.36,5738.69 cw(c15308.38,5752.67) 15294.4,5738.69 15289.83,5743.26 cw(c15303.81,5757.24) 15289.83,5771.22 15308.6,5789.99 ccw(c15303.81,5794.78) 15308.6,5799.57 15304.04,5804.13 ccw(c15299.25,5799.34) 15294.46,5804.13 15275.69,5785.36 cw(c15261.71,5799.34) 15247.73,5785.36 15243.16,5789.93 cw(c15257.14,5803.91) 15243.16,5817.89 ccw(c15238.37,5822.68) 15243.16,5827.46 15230.86,5839.77 15230.86,5864.03 ccw(c15223.36,5864.03) 15223.36,5871.53 15220.54,5871.53 cw(c15220.54,5892.03) 15220.54,5912.53 15223.36,5912.53 ccw(c15223.36,5920.03) 15223.36,5927.53 15220.54,5927.53 cw(c15220.54,5948.03) 15220.54,5968.53 15223.36,5968.53 ccw(c15223.36,5976.03) 15223.36,5983.53 15220.54,5983.53 cw(c15220.54,6004.03) 15220.54,6024.53 15223.36,6024.53 ccw(c15223.36,6032.03) 15230.86,6032.03 15230.86,6056.72 15227.52,6060.06 U3.24@15227.52,6091.59
DVI_C_D1+: D7.4 D7.7 U3.28 USB2.4 | length 1427.7
  Top Layer w4: USB2.4@15043.74,5258.81 15090.46,5258.81 15106.52,5274.88 15141.88,5274.88 15150.91,5283.9 15150.91,5322.89 15254.2,5426.18 15256.2,5426.18 15259.53,5422.85 D7.7@15274.92,5422.85 D7.4@15309.58,5422.85 15324.97,5422.85 15328.3,5426.18 15403.58,5426.18 15463.24,5485.85 15463.24,5551.29 cw(c15467.8,5551.29) 15467.8,5555.84 ccw(c15467.8,5573.4) 15485.36,5573.4 15485.36,5584.29 ccw(c15467.8,5584.29) 15467.8,5601.84 15445.69,5601.84 cw(c15445.69,5606.4) 15441.13,5606.4 15441.13,5617.29 cw(c15445.69,5617.29) 15445.69,5621.84 15467.8,5621.84 ccw(c15467.8,5639.4) 15485.36,5639.4 15485.36,5650.29 ccw(c15467.8,5650.29) 15467.8,5667.84 cw(c15467.8,5672.4) 15463.24,5672.4 15463.24,5704.92 15302.91,5865.25 15302.91,5912.23 cw(c15310.45,5912.23) 15310.45,5919.77 ccw(c15310.45,5940.31) 15330.99,5940.31 15330.99,5945.23 ccw(c15310.45,5945.23) 15310.45,5965.77 15282.37,5965.77 cw(c15282.37,5973.31) 15274.83,5973.31 15274.83,5978.23 cw(c15282.37,5978.23) 15282.37,5985.77 15310.45,5985.77 ccw(c15310.45,6006.31) 15330.99,6006.31 15330.99,6011.23 ccw(c15310.45,6011.23) 15310.45,6031.77 cw(c15310.45,6039.31) 15302.91,6039.31 15302.91,6056.72 15306.26,6060.06 U3.28@15306.26,6091.59
DVI_C_D1-: D7.5 D7.6 U3.27 USB2.6 | length 1426.3
  Top Layer w4: USB2.6@15045.04,5302.56 15046.98,5304.5 15090.99,5304.5 15106.52,5288.97 15106.52,5287.88 15136.49,5287.88 15137.91,5289.29 15137.91,5328.28 15171.01,5361.38 ccw(c15164.6,5367.79) 15171.01,5374.19 cw(c15177.42,5380.6) 15171.01,5387 15172.34,5388.33 cw(c15178.75,5381.93) 15185.15,5388.33 ccw(c15191.56,5394.74) 15197.97,5388.33 15248.81,5439.18 15256.2,5439.18 15259.53,5442.52 D7.6@15274.92,5442.52 15306.06,5442.52 D7.5@15307.88,5440.7 ; U3.27@15286.57,6091.59 15286.57,6060.06 15289.91,6056.72 15289.91,6039.31 ccw(c15310.45,6039.31) 15310.45,6018.77 cw(c15310.45,6011.23) 15317.99,6011.23 15317.99,6006.31 cw(c15310.45,6006.31) 15310.45,5998.77 15282.37,5998.77 ccw(c15282.37,5978.23) 15261.83,5978.23 15261.83,5973.31 ccw(c15282.37,5973.31) 15282.37,5952.77 15310.45,5952.77 cw(c15310.45,5945.23) 15317.99,5945.23 15317.99,5940.31 cw(c15310.45,5940.31) 15310.45,5932.77 ccw(c15310.45,5912.23) 15289.91,5912.23 15289.91,5859.87 15450.24,5699.54 15450.24,5672.4 ccw(c15467.8,5672.4) 15467.8,5654.84 cw(c15467.8,5650.29) 15472.36,5650.29 15472.36,5639.4 cw(c15467.8,5639.4) 15467.8,5634.84 15445.69,5634.84 ccw(c15445.69,5617.29) 15428.13,5617.29 15428.13,5606.4 ccw(c15445.69,5606.4) 15445.69,5588.84 15467.8,5588.84 cw(c15467.8,5584.29) 15472.36,5584.29 15472.36,5573.4 cw(c15467.8,5573.4) 15467.8,5568.84 ccw(c15467.8,5551.29) 15450.24,5551.29 15450.24,5491.23 15398.19,5439.18 15328.3,5439.18 15324.97,5442.52 D7.5@15309.57,5442.52
DVI_C_D2+: D7.1 D7.10 U3.31 USB2.1 | length 1429.6
  Top Layer w4: USB2.1@15082.22,5191.05 15082.22,5205.87 15083.63,5207.28 15123.42,5207.28 15170.78,5159.92 15225.73,5159.92 15252.78,5186.98 15252.78,5365.7 15254.2,5367.11 15256.2,5367.11 15259.53,5363.78 D7.10@15274.92,5363.78 15306.81,5363.78 D7.1@15308.2,5362.38 ; D7.1@15309.58,5363.78 15324.97,5363.78 15328.3,5367.11 15484.01,5367.11 15512.91,5396.01 15512.91,5724.31 15361.97,5875.25 15361.97,6056.72 15365.31,6060.06 U3.31@15365.31,6091.59
DVI_C_D2-: D7.2 D7.9 U3.30 USB2.3 | length 1433.3
  Top Layer w4: USB2.3@15082.22,5236.52 15082.22,5221.7 15083.63,5220.28 15128.81,5220.28 15176.17,5172.92 15220.34,5172.92 15239.78,5192.36 15239.78,5371.08 15248.81,5380.11 15256.2,5380.11 15259.53,5383.45 D7.9@15274.92,5383.45 15307.2,5383.45 D7.2@15308.52,5382.12 ; D7.2@15309.58,5383.45 15324.97,5383.45 15328.3,5380.11 15415.95,5380.11 ccw(c15415.95,5390.11) 15425.95,5390.11 15425.95,5391.13 cw(c15435.95,5391.13) 15445.95,5391.13 15445.95,5390.11 ccw(c15455.95,5390.11) 15455.95,5380.11 15478.62,5380.11 15499.91,5401.4 15499.91,5718.92 15348.97,5869.86 15348.97,6056.72 15345.63,6060.06 U3.30@15345.63,6091.59
DVI_HPD: Q6.3 U8.W11 U27.1 | length 3149.5
  Top Layer w4.7: v3(14566.36,7604) 14583.08,7620.73 U8.W11@14587.66,7620.73 ; Q6.3@16582.98,5771.08 16582.98,5836.37 U27.1@16583.32,5836.71 ; U27.1@16583.36,5836.74 v3(16583.36,5886)
  L3_SIG1 w5: v3(14566.36,7604) 14566.36,7599 14583.36,7582 14583.36,7321 14791.36,7113 15564.36,7113 16583.36,6094 v3(16583.36,5886)
DVI_HPD_EXT: D12.4 Q5.1 U25.2 USB2.19 | length 1541.2
  Top Layer w4.7: v3(15986.36,5685) 15988.32,5683.04 D12.4@15988.32,5641.45 v3(15988.32,5603) ; v3(16308.36,5612) 16390.25,5612 Q5.1@16390.58,5612.34 16398.32,5604.6 U25.2@16398.32,5536.71
  L6_SIG2 w5: USB2.19@15082.22,5600.3 15119.52,5563 15725.36,5563 15851.36,5689 15982.36,5689 v3(15986.36,5685) ; v3(15988.32,5603) 16299.36,5603 v3(16308.36,5612)
DVI_SCL: D12.1 Q8.3 R107.1 U19.2 U19.3 USB2.15 | length 1949.2
  Top Layer w4.7: v3(15913.36,5484) 15913.52,5484.16 D12.1@15913.52,5531.21 ; v3(15913.36,5577) 15913.36,5531.37 D12.1@15913.52,5531.21 ; v3(16012.36,5325.41) U19.3@16078.46,5325.41 U19.2@16078.46,5275.41 16016.77,5275.41 16007.36,5266 16007.36,5192 16019.36,5180 16159.52,5180 Q8.3@16199.94,5220.41 ; R107.1@16070.27,5496.33 16070.27,5530.09 16037.36,5563 15933.36,5563 15913.52,5543.16 D12.1@15913.52,5531.21
  L6_SIG2 w5: USB2.15@15082.22,5509.36 15107.58,5484 v3(15913.36,5484) ; v3(15913.36,5577) 15944.36,5577 15949.36,5572 15949.36,5388.41 v3(16012.36,5325.41)
DVI_SDA: D12.6 Q7.3 R106.2 U19.5 U19.6 USB2.16 | length 1850.4
  Top Layer w4.7: U19.6@15860.16,5325.41 U19.5@15860.16,5375.41 ; v3(15912.36,5603) D12.6@15912.36,5640.29 ; R106.2@16069.32,5697 16068.32,5698 15936.36,5698 15913.52,5675.16 D12.6@15913.52,5641.45 D12.6@15912.36,5640.29 ; Q7.3@16199.94,5375.41 16176.35,5399 15883.75,5399 U19.5@15860.16,5375.41 ; U19.5@15860.16,5375.41 15860.16,5617.8 15881.36,5639 15911.07,5639 D12.6@15912.36,5640.29
  L6_SIG2 w5: USB2.16@15042.85,5532.03 15775.39,5532.03 15846.36,5603 v3(15912.36,5603)
DW_A0: R64.1 U8.F21 U12.N3 | length 1126.7
  Top Layer w4.7: R64.1@15395.82,8489.37 15395.82,8466.6 15417.22,8445.21 15417.22,8246.69 15428.6,8235.3 U12.N3@15441.89,8235.3 ; U12.N3@15445.35,8237.73 v2(15461.09,8253.48)
  Top Layer w7.9: U8.F21@14981.36,8132.53 v2(15001.04,8152.21)
  L3_SIG1 w5: v2(15001.04,8152.21) 15020.23,8171.4 15042.14,8171.4 15170.83,8300.1 ccw(c15170.83,8305.1) 15175.83,8305.1 15175.83,8312.02 cw(c15180.83,8312.02) 15185.83,8312.02 15185.83,8305.1 ccw(c15190.83,8305.1) 15195.83,8305.1 15195.83,8312.02 cw(c15200.83,8312.02) 15205.83,8312.02 15205.83,8305.1 ccw(c15210.83,8305.1) 15215.83,8305.1 15215.83,8312.02 cw(c15220.83,8312.02) 15225.83,8312.02 15225.83,8305.1 ccw(c15230.83,8305.1) 15230.83,8300.1 15327.62,8300.1 ccw(c15327.62,8305.1) 15332.62,8305.1 15332.62,8311.07 cw(c15337.62,8311.07) 15342.62,8311.07 15342.62,8305.1 ccw(c15347.62,8305.1) 15352.62,8305.1 15352.62,8311.07 cw(c15357.62,8311.07) 15362.62,8311.07 15362.62,8305.1 ccw(c15367.62,8305.1) 15367.62,8300.1 15375.43,8300.1 15399.22,8276.3 ccw(c15402.76,8279.84) 15406.29,8276.3 15416.24,8286.25 cw(c15419.78,8282.72) 15423.32,8279.18 15413.37,8269.23 ccw(c15416.9,8265.7) 15420.44,8262.16 15430.39,8272.11 cw(c15433.92,8268.57) 15437.46,8265.04 15427.51,8255.09 ccw(c15431.04,8251.55) 15427.51,8248.02 15439.09,8236.44 15470.97,8236.44 15478.65,8244.11 15478.65,8250.67 15475.46,8253.85 15461.47,8253.85 v2(15461.09,8253.48)
DW_A1: R69.1 U8.F22 U12.P7 | length 1168.2
  Top Layer w4.7: v3(15253.28,8466.31) 15253.28,8418.62 15264.93,8406.97 15309.71,8406.97 15346.21,8370.47 15346.21,8299.2 15331.99,8284.98 v2(15303.62,8284.98) U12.P7@15319.37,8269.23
  Top Layer w7.9: U8.F22@15020.76,8132.53 v2(15040.44,8152.21)
  Bottom Layer w3.5: 15276.07,8143.81 15284.27,8152.02 15284.27,8200.52 15284.14,8200.65
  Bottom Layer w4: 15284.14,8200.65 15284.37,8200.88
  Bottom Layer w4.7: v2(15040.44,8152.21) 15056.45,8168.22 15090.35,8168.22 cw(c15086.82,8164.69) 15090.35,8161.15 15056.79,8127.59 ccw(c15060.33,8124.06) 15063.86,8120.52 15097.42,8154.08 cw(c15100.96,8150.54) 15104.49,8147.01 15070.93,8113.45 ccw(c15074.47,8109.91) 15078,8106.38 15111.56,8139.94 cw(c15115.1,8136.4) 15118.64,8132.87 15085.08,8099.31 ccw(c15088.61,8095.77) 15092.15,8092.24 15125.71,8125.8 cw(c15129.24,8122.26) 15132.78,8125.8 15154.17,8104.4 15218.12,8104.4 15257.54,8143.81 15276.07,8143.81 ; R69.1@15237.02,8491.31 15237.02,8471.68 15242.39,8466.31 v3(15253.28,8466.31) ; 15284.37,8200.88 15279.22,8206.03 15263.3,8206.03 15254.88,8214.46 15254.88,8225.41 15267.1,8237.63 15279.1,8237.63 15285.21,8243.74 15285.21,8269.64 15285,8269.86 ; 15284.98,8270.09 15285.23,8270.09 15300.11,8284.98 v2(15303.62,8284.98)
DW_A2: R68.1 U8.E22 U12.P3 | length 1102.8
  Top Layer w4.7: U12.P3@15443.07,8267.73 15431.8,8267.73 15425.42,8274.12 15425.42,8382.46 15477.58,8434.62 15477.58,8488.42 R68.1@15478.06,8488.9 ; U12.P3@15445.35,8269.23 v2(15461.09,8284.98)
  Top Layer w7.9: U8.E22@15020.76,8171.9 v2(15040.44,8191.57)
  L3_SIG1 w5: v2(15040.44,8191.57) 15040.44,8203.89 15057.87,8221.33 ccw(c15054.34,8224.86) 15057.87,8228.4 15055.68,8230.59 cw(c15059.21,8234.13) 15062.75,8237.66 15064.94,8235.47 ccw(c15068.48,8239.01) 15072.01,8242.54 15069.82,8244.73 cw(c15073.36,8248.27) 15076.89,8251.8 15079.08,8249.61 ccw(c15082.62,8253.15) 15086.16,8256.68 15083.96,8258.88 cw(c15087.5,8262.41) 15091.03,8265.95 15093.23,8263.75 ccw(c15096.76,8267.29) 15100.3,8263.75 15169.12,8332.58 15195.06,8332.58 ccw(c15195.06,8337.58) 15200.06,8337.58 15200.06,8343.13 cw(c15205.06,8343.13) 15210.06,8343.13 15210.06,8337.58 ccw(c15215.06,8337.58) 15215.06,8332.58 15333.92,8332.58 ccw(c15333.92,8337.58) 15338.92,8337.58 15338.92,8342.66 cw(c15343.92,8342.66) 15348.92,8342.66 15348.92,8337.58 ccw(c15353.92,8337.58) 15358.92,8337.58 15358.92,8342.66 cw(c15363.92,8342.66) 15368.92,8342.66 15368.92,8337.58 ccw(c15373.92,8337.58) 15373.92,8332.58 15385.17,8332.58 15395.14,8322.61 ccw(c15398.67,8326.15) 15402.21,8322.61 15413.31,8333.71 cw(c15416.84,8330.18) 15420.38,8326.64 15409.28,8315.54 ccw(c15412.81,8312.01) 15409.28,8308.47 15415.91,8301.84 15506.75,8301.84 15508.86,8299.73 15508.86,8271.09 15505.49,8267.72 15475.16,8267.72 15461.09,8281.78 v2(15461.09,8284.98)
DW_A3: R63.1 U8.G20 U12.N2 | length 1132.6
  Top Layer w4.7: R63.1@15437.53,8490.51 15436.91,8489.9 15436.91,8469.35 15440.29,8465.98 v3(15453.17,8465.98) ; U12.N2@15476.85,8237.73 v2(15492.59,8253.48)
  Top Layer w7.9: U8.G20@14942,8093.16 v2(14961.68,8112.84)
  L6_SIG2 w5: v2(14961.68,8112.84) 14957.21,8112.84 14938.92,8094.55 14906.06,8094.55 14897.21,8103.4 14897.21,8120.58 cw(c14902.21,8120.58) 14902.21,8125.58 14908.51,8125.58 ccw(c14908.51,8130.58) 14908.51,8135.58 14902.21,8135.58 cw(c14902.21,8140.58) 14897.21,8140.58 14897.21,8151.74 14924.19,8178.72 15207.29,8178.72 15219.17,8190.6 15253.2,8190.6 15267.73,8205.14 15467.26,8205.14 15476.41,8214.28 15476.41,8237.9 15491.98,8253.48 v2(15492.59,8253.48) 15476.4,8269.67 15476.4,8386.85 15435,8428.25 15435,8447.8 v3(15453.17,8465.98)
  Bottom Layer w7.9: v3@15453.17,8465.82 v3(15453.17,8465.98)
DW_A4: R70.1 U8.F20 U12.P8 | length 1449
  Top Layer w4.7: v2(15272.12,8284.98) U12.P8@15287.87,8269.23
  Top Layer w7.9: U8.F20@14942,8132.53 v2(14961.68,8152.21)
  L6_SIG2 w5: v3(15179.78,8456.42) 15179.78,8423.76 15195.81,8407.73 15423.35,8407.73 15446.58,8384.5 15446.58,8328.83 15432.32,8314.57 15325.81,8314.57 15310.4,8299.15 15286.3,8299.15 v2(15272.12,8284.98)
  Bottom Layer w4.7: v2(14961.68,8152.21) 14961.81,8152.34 14979.92,8152.34 15017.41,8189.84 15017.41,8198.19 15007.77,8207.83 14990.08,8207.83 14986.33,8211.58 14986.33,8238.73 14992.14,8244.53 15052.12,8244.53 15067.92,8228.73 15090.24,8228.73 ccw(c15090.24,8233.73) 15095.24,8233.73 15095.24,8267.47 cw(c15100.24,8267.47) 15105.24,8267.47 15105.24,8233.73 ccw(c15110.24,8233.73) 15115.24,8233.73 15115.24,8267.47 cw(c15120.24,8267.47) 15125.24,8267.47 15125.24,8233.73 ccw(c15130.24,8233.73) 15135.24,8233.73 15135.24,8267.47 cw(c15140.24,8267.47) 15145.24,8267.47 15145.24,8233.73 ccw(c15150.24,8233.73) 15155.24,8233.73 15155.24,8267.47 cw(c15160.24,8267.47) 15165.24,8267.47 15165.24,8233.73 ccw(c15170.24,8233.73) 15170.24,8228.73 15224.54,8228.73 15233.39,8237.58 15253.39,8237.58 15256.87,8241.06 15256.87,8269.72 v2(15272.12,8284.98) ; v3(15179.78,8456.42) v3@15179.9,8456.54 ; v3@15180.13,8456.77 15196.81,8473.45 R70.1@15196.81,8490.24
  Bottom Layer w7.9: v3(15179.78,8456.42) v3@15179.78,8456.65 ; v3@15179.9,8456.54 v3@15180.13,8456.77
DW_A5: R67.1 U8.K20 U12.P2 | length 1080.4
  Top Layer w4.7: U12.P2@15476.85,8269.23 v2(15492.59,8284.98)
  Top Layer w7.9: U8.K20@14942,7975.06 v2(14961.68,7994.73)
  L6_SIG2 w5: v3(15491.96,8463.21) 15508.98,8446.19 15508.98,8301.36 v2(15492.59,8284.98)
  Bottom Layer w4.7: v2(14961.68,7994.73) 14961.68,7992.54 14974.97,7979.25 15051.75,7979.25 15122.53,8050.03 15252.07,8050.03 15258.08,8056.03 15258.08,8078.15 15275.45,8095.52 15376.88,8095.52 15388.88,8107.53 15388.88,8136.91 15429.64,8177.67 ccw(c15429.64,8182.67) 15434.64,8182.67 15434.64,8204.24 cw(c15439.64,8204.24) 15444.64,8204.24 15444.64,8182.67 ccw(c15449.64,8182.67) 15449.64,8177.67 15467.4,8177.67 15478.3,8188.57 15478.3,8270.68 v2(15492.59,8284.98) ; R67.1@15476.78,8489.89 15476.08,8489.2 15476.08,8469.42 15482.99,8462.52 v3@15491.96,8462.52
  Bottom Layer w7.9: v3@15491.96,8462.52 v3(15491.96,8463.21)
DW_A6: R74.1 U8.K19 U12.R8 | length 1221.9
  Top Layer w4.7: v2(15272.12,8316.47) U12.R8@15287.87,8300.72
  Top Layer w7.9: U8.K19@14902.63,7975.06 v2(14922.31,7994.73)
  Bottom Layer w3.5: 15291.22,8128.23 15291.22,8165.98 15301.79,8176.54
  Bottom Layer w4: 15257.49,8094.5 15291.22,8128.23 ; 15283.99,8304.59 15284.5,8304.09 15309.78,8304.09 15310.28,8304.59
  Bottom Layer w4.7: v2(14922.31,7994.73) 14939.92,8012.34 15051.81,8012.34 15133.97,8094.5 15257.49,8094.5 ; R74.1@15156.99,8493.05 15156.99,8404.03 15182.52,8378.5 15297.08,8378.5 15318.82,8356.76 15318.82,8313.13 15310.28,8304.59 ; 15283.99,8304.59 v2(15272.12,8316.47) 15272.12,8305.19 15279.52,8297.79 15327.38,8297.79 15344.29,8280.88 ccw(c15349.29,8280.88) 15349.29,8275.88 15366.8,8275.88 cw(c15366.8,8270.88) 15366.8,8265.88 15349.29,8265.88 ccw(c15349.29,8260.88) 15349.29,8255.88 15366.8,8255.88 cw(c15366.8,8250.88) 15366.8,8245.88 15349.29,8245.88 ccw(c15349.29,8240.88) 15344.29,8240.88 15344.29,8190.02 15330.81,8176.54 15301.79,8176.54
DW_A7: R71.1 U8.E20 U12.R2 | length 1075.7
  Top Layer w4.7: U12.R2@15476.85,8300.72 v2(15492.59,8316.47)
  Top Layer w7.9: U8.E20@14942,8171.9 v2(14961.68,8191.57)
  L3_SIG1 w5: v2(14961.68,8191.57) 14942.11,8211.14 14917.36,8211.14 14908.85,8219.65 14908.85,8237.03 14961.63,8289.81 15002.66,8289.81 15020.48,8307.64 15020.48,8320.7 15028.38,8328.6 15040.64,8328.6 15129.98,8417.94 15418.62,8417.94 15476.28,8360.27 15476.28,8332.77 v2(15492.59,8316.47)
  Bottom Layer w4.7: v2(15492.59,8316.47) 15508.82,8332.7 15531.05,8332.7 15543.36,8345.01 15543.36,8465.07 R71.1@15517.47,8490.96
DW_A8: R77.1 U8.C20 U12.T8 | length 1086.1
  Top Layer w4.7: R77.1@15158.73,8489.29 15158.73,8384.74 15176.67,8366.8 15263.62,8366.8 15272.12,8358.3 v2(15272.12,8347.97) U12.T8@15287.87,8332.22
  Top Layer w7.9: U8.C20@14942,8250.65 v2(14961.68,8270.32)
  L6_SIG2 w5: v2(14961.68,8270.32) 14984.61,8293.25 15064.8,8293.25 ccw(c15064.8,8298.25) 15069.8,8298.25 15069.8,8335.72 cw(c15074.8,8335.72) 15079.8,8335.72 15079.8,8298.25 ccw(c15084.8,8298.25) 15089.8,8298.25 15089.8,8335.72 cw(c15094.8,8335.72) 15099.8,8335.72 15099.8,8298.25 ccw(c15104.8,8298.25) 15109.8,8298.25 15109.8,8335.72 cw(c15114.8,8335.72) 15119.8,8335.72 15119.8,8298.25 ccw(c15124.8,8298.25) 15124.8,8293.25 15140.61,8293.25 15160.88,8313.52 ccw(c15157.34,8317.06) 15160.88,8320.59 15144.07,8337.4 cw(c15147.61,8340.94) 15151.14,8344.47 15167.95,8327.66 ccw(c15171.49,8331.2) 15175.02,8334.73 15158.21,8351.54 cw(c15161.75,8355.08) 15165.28,8358.61 15182.09,8341.81 ccw(c15185.63,8345.34) 15189.16,8348.88 15172.35,8365.68 cw(c15175.89,8369.22) 15179.43,8372.76 15196.23,8355.95 ccw(c15199.77,8359.48) 15203.31,8355.95 15217.39,8370.03 15250.06,8370.03 v2(15272.12,8347.97)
